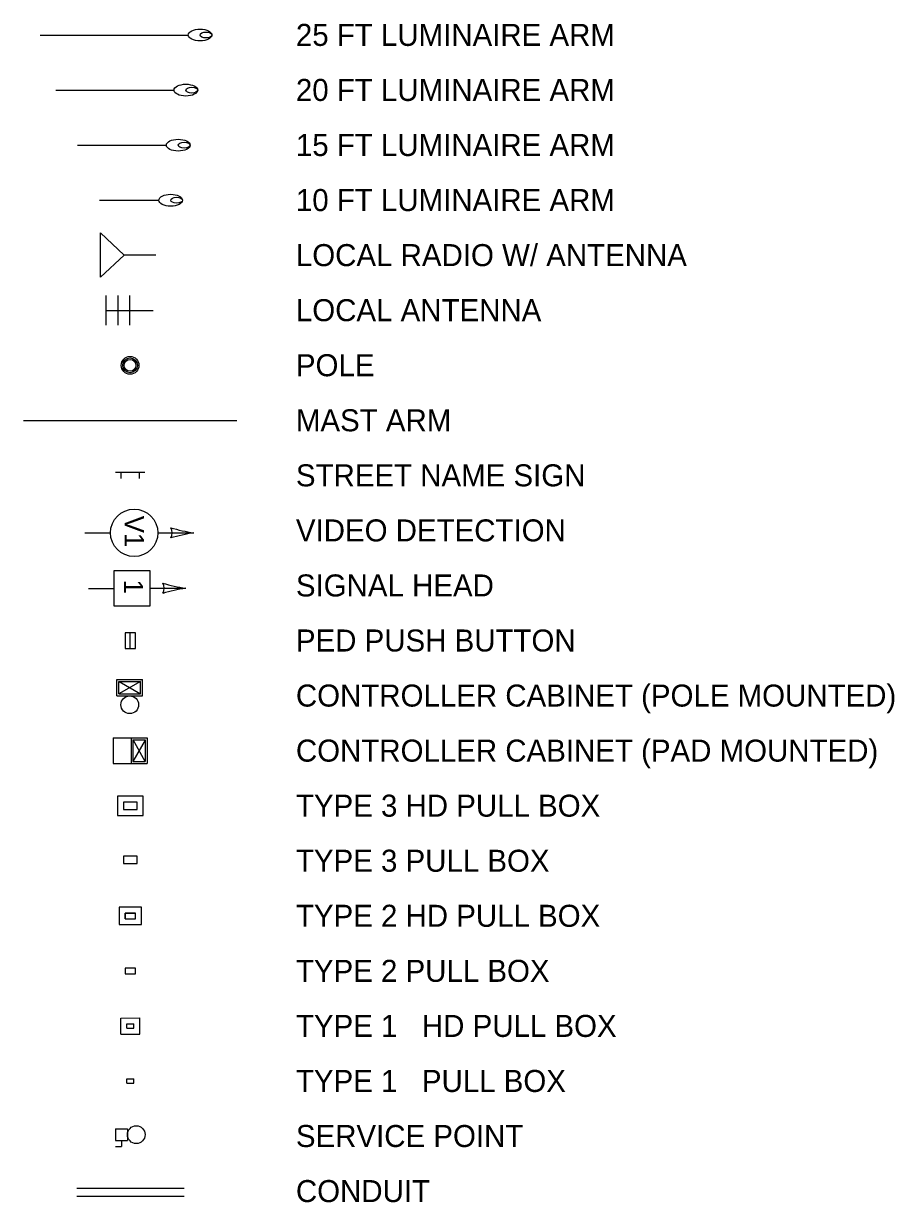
# Model space of a CAD drawing. Extents: x 995226 to 996234, y 1982095 to 1983315.
# Drawn here: x 996021.3 to 996168.4, y 1983115.6 to 1983314.7 of the extents above; entities that cross this region are included whole.
import ezdxf

# ---------------------------------------------------------------- set-up
doc = ezdxf.new("R2010")
doc.units = 0
for name, color, linetype in [('S_CROSS_DRAIN', 7, 'Continuous'), ('S_CURB', 7, 'Continuous'), ('S_DRIVEWAY', 7, 'Continuous'), ('S_EDGE_PAVEMENT', 7, 'Continuous'), ('S_PAVEMENT_CROWN', 7, 'Continuous'), ('S_SIDE_DRAIN', 7, 'Continuous'), ('S_SIDEWALK', 7, 'Continuous'), ('S_WALL', 7, 'Continuous'), ('S_WALL_ANNOT', 7, 'Continuous')]:
    doc.layers.add(name, color=color, linetype=linetype)

msp = doc.modelspace()

# ---------------------------------------------------------------- linework, layer by layer
at = {"layer": 'S_CROSS_DRAIN'}
msp.add_lwpolyline([(996038.45, 1983211.81), (996038.45, 1983209.18), (996039.32, 1983209.18), (996039.32, 1983211.81)], close=True, dxfattribs=at)
at = {"layer": 'S_CURB'}
for p, q in [((996036.45, 1983194.06), (996042.19, 1983194.06)), ((996036.45, 1983194.06), (996036.45, 1983189.73)), ((996039.45, 1983194.06), (996039.45, 1983189.73)), ((996042.19, 1983194.06), (996042.19, 1983189.73)), ((996039.78, 1983193.73), (996039.78, 1983190.06)), ((996039.78, 1983193.73), (996041.86, 1983193.73)), ((996041.86, 1983193.71), (996039.78, 1983190.06)), ((996041.86, 1983190.06), (996039.79, 1983193.73)), ((996041.86, 1983193.73), (996041.86, 1983190.06)), ((996039.78, 1983190.06), (996041.86, 1983190.06)), ((996036.45, 1983189.73), (996042.19, 1983189.73))]:
    msp.add_line(p, q, dxfattribs=at)
at = {"layer": 'S_DRIVEWAY'}
for p, q in [((996036.84, 1983128.05), (996036.84, 1983126.05)), ((996036.84, 1983128.05), (996038.84, 1983128.05)), ((996038.84, 1983128.05), (996038.84, 1983126.05)), ((996036.84, 1983126.05), (996038.84, 1983126.05)), ((996036.84, 1983125.05), (996037.84, 1983125.05)), ((996037.84, 1983126.05), (996037.84, 1983125.05)), ((996030.27, 1983117.99), (996048.41, 1983117.99)), ((996030.27, 1983116.66), (996048.41, 1983116.67))]:
    msp.add_line(p, q, dxfattribs=at)
msp.add_circle((996040.34, 1983127.05), 1.5, dxfattribs=at)
at = {"layer": 'S_EDGE_PAVEMENT'}
msp.add_line((996021.3, 1983247.69), (996057.3, 1983247.71), dxfattribs=at)
for radius in [1.5, 1.25, 1]:
    msp.add_circle((996039.29, 1983257), radius, dxfattribs=at)
at = {"layer": 'S_PAVEMENT_CROWN'}
for p, q in [((996031.65, 1983228.7), (996035.98, 1983228.7)), ((996043.98, 1983228.71), (996050.04, 1983228.71)), ((996032.24, 1983219.32), (996036.59, 1983219.32)), ((996042.65, 1983219.35), (996048.69, 1983219.35))]:
    msp.add_line(p, q, dxfattribs=at)
msp.add_lwpolyline([(996036.59, 1983216.31), (996036.59, 1983222.37), (996042.65, 1983222.37), (996042.65, 1983216.31)], close=True, dxfattribs=at)
msp.add_circle((996039.98, 1983228.71), 4, dxfattribs=at)
for centre, radius, start, end in [((996044.77, 1983228.71), 1.63, 328.1778, 31.8725), ((996054.44, 1983257.85), 29.47, 253.6787, 261.4168), ((996054.47, 1983199.57), 29.47, 98.6335, 106.3716), ((996043.42, 1983219.35), 1.63, 328.1778, 31.8725), ((996053.09, 1983248.49), 29.47, 253.6787, 261.4168), ((996053.11, 1983190.21), 29.47, 98.6335, 106.3716)]:
    msp.add_arc(centre, radius, start, end, dxfattribs=at)
at = {"layer": 'S_SIDE_DRAIN'}
for p, q in [((996041.8, 1983238.89), (996036.8, 1983238.89)), ((996037.8, 1983237.89), (996037.8, 1983238.89)), ((996040.8, 1983238.89), (996040.8, 1983237.89)), ((996041.8, 1983238.89), (996040.8, 1983238.89))]:
    msp.add_line(p, q, dxfattribs=at)
at = {"layer": 'S_SIDEWALK'}
for p, q in [((996041.49, 1983184.23), (996037.16, 1983184.22)), ((996037.16, 1983184.22), (996037.16, 1983180.95)), ((996041.5, 1983180.96), (996041.49, 1983184.23)), ((996040.49, 1983183.23), (996038.16, 1983183.22)), ((996038.16, 1983183.22), (996038.16, 1983181.95)), ((996038.16, 1983181.95), (996040.49, 1983181.96)), ((996040.49, 1983181.96), (996040.49, 1983183.23)), ((996037.16, 1983180.95), (996041.5, 1983180.96)), ((996038.16, 1983174.1), (996038.16, 1983172.83)), ((996040.49, 1983174.1), (996038.16, 1983174.1)), ((996040.49, 1983172.83), (996040.49, 1983174.1)), ((996038.16, 1983172.83), (996040.49, 1983172.83)), ((996041.2, 1983165.45), (996037.45, 1983165.45)), ((996037.45, 1983165.45), (996037.45, 1983162.53)), ((996038.45, 1983163.53), (996038.45, 1983164.45)), ((996038.45, 1983164.45), (996040.2, 1983164.45)), ((996038.45, 1983164.45), (996038.45, 1983163.53)), ((996040.2, 1983164.45), (996038.45, 1983164.45)), ((996040.2, 1983163.53), (996040.2, 1983164.45)), ((996040.2, 1983163.53), (996040.2, 1983164.45)), ((996041.2, 1983162.53), (996041.2, 1983165.45)), ((996037.45, 1983162.53), (996041.2, 1983162.53)), ((996038.45, 1983163.53), (996040.2, 1983163.53)), ((996038.45, 1983163.53), (996040.2, 1983163.53)), ((996038.46, 1983155.15), (996038.46, 1983154.23)), ((996040.21, 1983155.15), (996038.46, 1983155.15)), ((996038.46, 1983154.23), (996040.21, 1983154.23)), ((996040.21, 1983154.23), (996040.21, 1983155.15))]:
    msp.add_line(p, q, dxfattribs=at)
msp.add_lwpolyline([(996038.45, 1983209.18), (996040.19, 1983209.17), (996040.19, 1983211.81), (996038.45, 1983211.81)], close=True, dxfattribs=at)
at = {"layer": 'S_WALL'}
for p, q in [((996024.12, 1983312.78), (996049.12, 1983312.79)), ((996026.72, 1983303.48), (996046.72, 1983303.49)), ((996030.43, 1983294.19), (996045.43, 1983294.19)), ((996034.15, 1983284.89), (996044.15, 1983284.89)), ((996034.28, 1983271.87), (996034.28, 1983279.37)), ((996034.28, 1983279.37), (996038.28, 1983275.62)), ((996038.28, 1983275.62), (996034.28, 1983271.87)), ((996043.63, 1983275.62), (996038.28, 1983275.62)), ((996035.21, 1983268.78), (996035.21, 1983263.78)), ((996037.21, 1983268.78), (996037.21, 1983263.78)), ((996039.21, 1983268.78), (996039.21, 1983263.78)), ((996035.21, 1983266.28), (996043.21, 1983266.29)), ((996037.07, 1983201.17), (996037.07, 1983203.91)), ((996037.07, 1983203.91), (996041.4, 1983203.91)), ((996041.4, 1983201.17), (996041.4, 1983203.91)), ((996037.4, 1983203.58), (996041.07, 1983203.58)), ((996037.4, 1983201.5), (996037.4, 1983203.58)), ((996041.07, 1983203.58), (996037.4, 1983201.5)), ((996037.42, 1983203.58), (996041.07, 1983201.5)), ((996041.07, 1983201.5), (996041.07, 1983203.58)), ((996037.07, 1983201.17), (996041.4, 1983201.17)), ((996037.4, 1983201.5), (996041.07, 1983201.5)), ((996037.74, 1983146.75), (996040.93, 1983146.76)), ((996037.74, 1983144.03), (996037.74, 1983146.75)), ((996040.93, 1983144.03), (996040.93, 1983146.76)), ((996038.74, 1983145.75), (996039.93, 1983145.76)), ((996038.74, 1983145.03), (996038.74, 1983145.75)), ((996038.74, 1983145.03), (996039.93, 1983145.03)), ((996039.93, 1983145.03), (996039.93, 1983145.76)), ((996037.74, 1983144.03), (996040.93, 1983144.03)), ((996038.75, 1983135.73), (996038.75, 1983136.46)), ((996038.75, 1983136.46), (996039.93, 1983136.46)), ((996039.93, 1983135.73), (996039.93, 1983136.46)), ((996038.75, 1983135.73), (996039.93, 1983135.73))]:
    msp.add_line(p, q, dxfattribs=at)
msp.add_circle((996039.24, 1983199.67), 1.5, dxfattribs=at)
for centre, major_axis in [((996051.12, 1983312.8), (2, 0)), ((996052.12, 1983312.8), (-1, 0)), ((996048.72, 1983303.49), (2, 0)), ((996049.72, 1983303.49), (-1, 0)), ((996047.43, 1983294.19), (2, 0)), ((996048.43, 1983294.19), (-1, 0)), ((996046.15, 1983284.89), (2, 0)), ((996047.15, 1983284.89), (-1, 0))]:
    msp.add_ellipse(centre, major_axis=major_axis, ratio=0.5, dxfattribs=at)

# ---------------------------------------------------------------- texts
at = {"layer": 'S_PAVEMENT_CROWN'}
for s, p in [('V1', (996038.38, 1983231.59)), ('1', (996038.24, 1983220.81))]:
    msp.add_text(s, height=3.25, rotation=270.0252, dxfattribs=at).set_placement(p)
at = {"layer": 'S_WALL_ANNOT'}
for s, p in [('25 FT LUMINAIRE ARM', (996067.31, 1983310.96)), ('20 FT LUMINAIRE ARM', (996067.31, 1983301.66)), ('15 FT LUMINAIRE ARM', (996067.31, 1983292.36)), ('10 FT LUMINAIRE ARM', (996067.31, 1983283.06)), ('LOCAL RADIO W/ ANTENNA', (996067.31, 1983273.76)), ('LOCAL ANTENNA', (996067.31, 1983264.46)), ('POLE', (996067.31, 1983255.16)), ('MAST ARM', (996067.31, 1983245.86)), ('STREET NAME SIGN', (996067.31, 1983236.56)), ('VIDEO DETECTION', (996067.31, 1983227.26)), ('SIGNAL HEAD', (996067.31, 1983217.96)), ('PED PUSH BUTTON', (996067.31, 1983208.66)), ('CONTROLLER CABINET (POLE MOUNTED)', (996067.31, 1983199.36)), ('CONTROLLER CABINET (PAD MOUNTED)', (996067.31, 1983190.06)), ('TYPE 3 HD PULL BOX', (996067.31, 1983180.76)), ('TYPE 3 PULL BOX', (996067.31, 1983171.46)), ('TYPE 2 HD PULL BOX', (996067.31, 1983162.16)), ('TYPE 2 PULL BOX', (996067.31, 1983152.86)), ('TYPE 1   HD PULL BOX', (996067.31, 1983143.56)), ('TYPE 1   PULL BOX', (996067.31, 1983134.26)), ('SERVICE POINT', (996067.31, 1983124.96)), ('CONDUIT', (996067.31, 1983115.66))]:
    msp.add_text(s, height=3.72, dxfattribs=at).set_placement(p)

doc.saveas('drawing.dxf')
